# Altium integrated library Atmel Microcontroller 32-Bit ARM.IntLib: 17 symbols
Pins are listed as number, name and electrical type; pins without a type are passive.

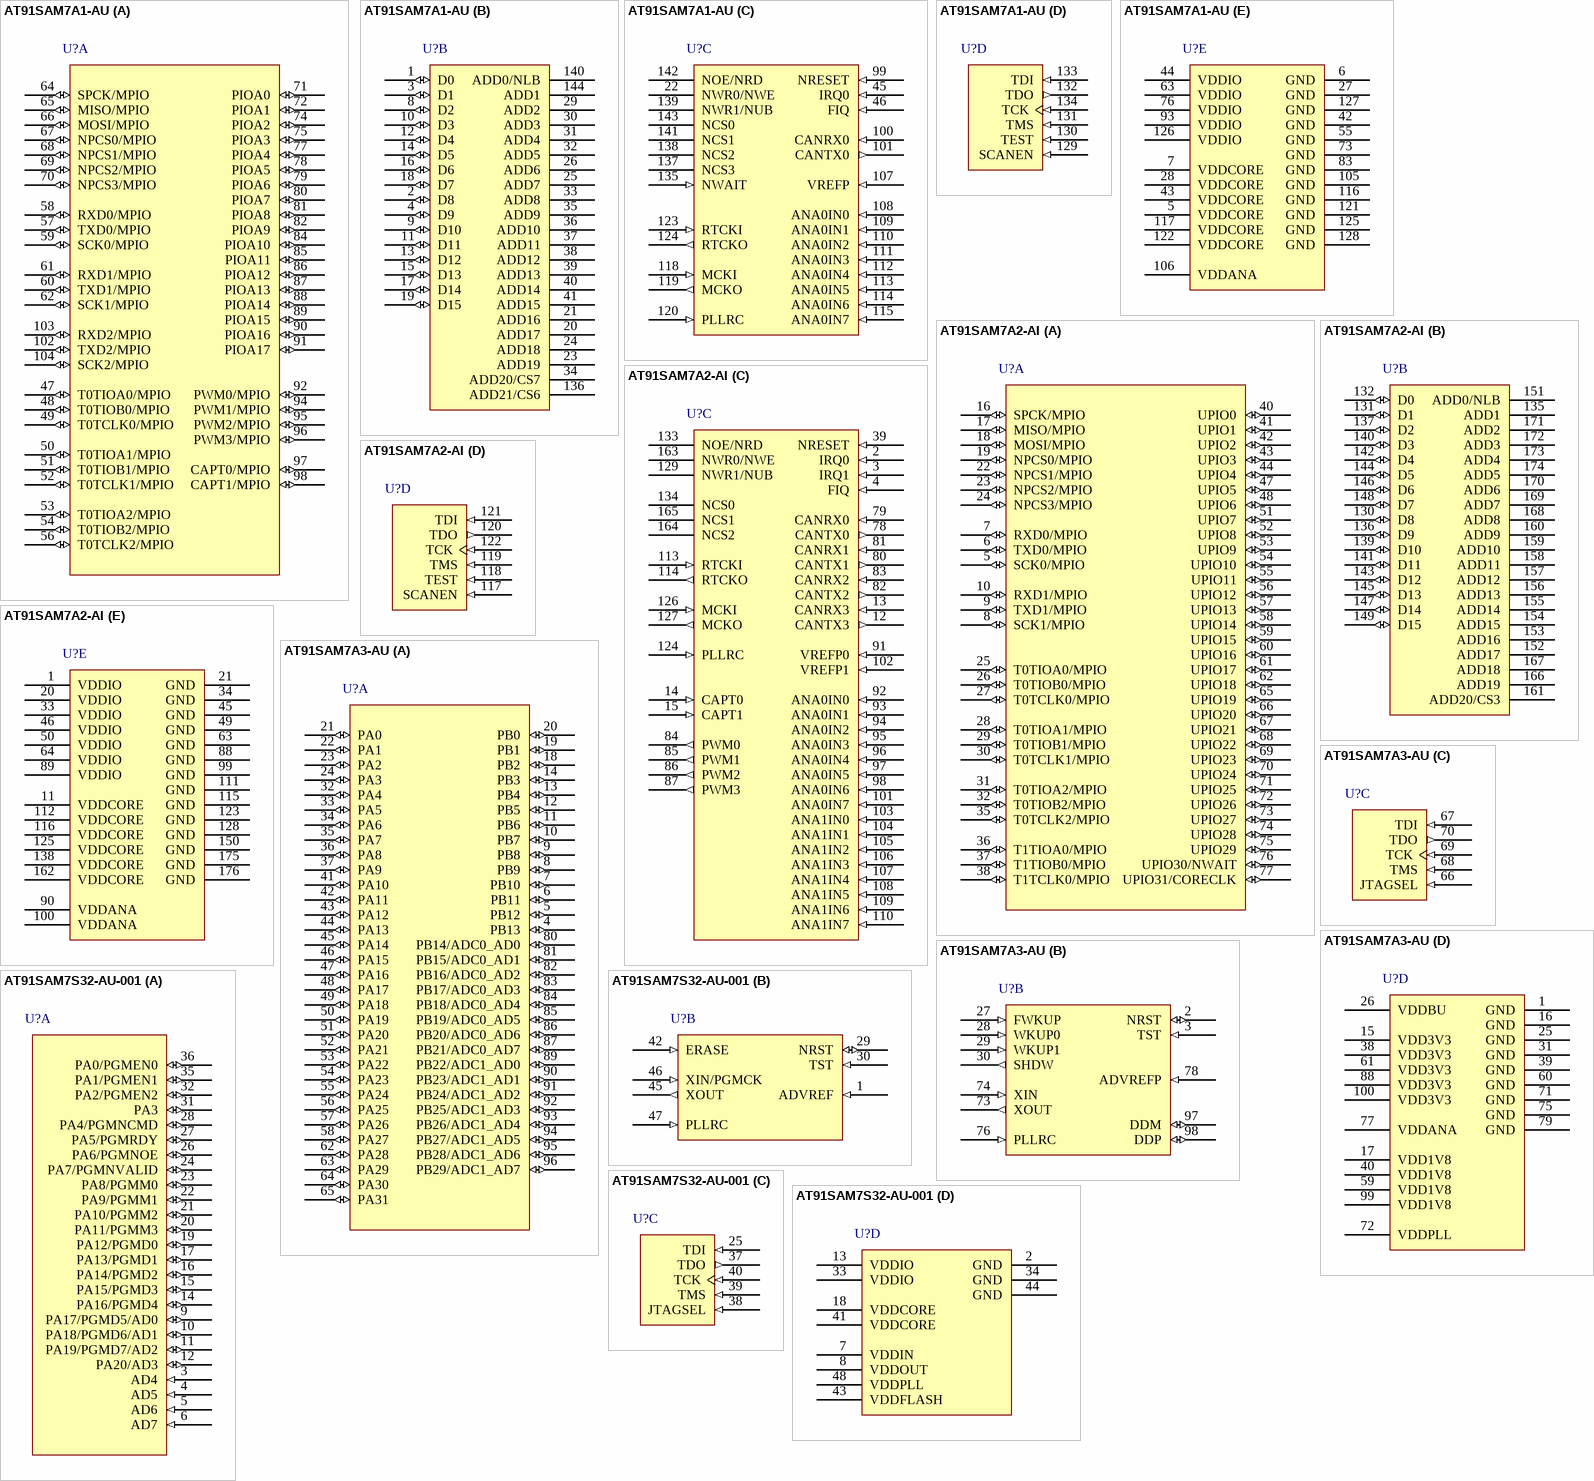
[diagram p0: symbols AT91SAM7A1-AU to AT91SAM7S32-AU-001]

## AT91SAM7A1-AU
designator U?
Smart ARM Microcontroller, ARM7TDMI 32-Bit RISC CPU, 4KB Internal RAM, 144-Pin LQFP, Industrial, Pb-Free
footprint 144AA_N (Thin QFP, 144-Leads, Body 20x20mm, Pitch 0.5mm, IPC Medium Density)
footprint 144AA_L (Thin QFP, 144-Leads, Body 20x20mm, Pitch 0.5mm, IPC High Density)
footprint 144AA_M (Thin QFP, 144-Leads, Body 20x20mm, Pitch 0.5mm, IPC Low Density)
part A pins: 47 T0TIOA0/MPIO (io), 48 T0TIOB0/MPIO (io), 49 T0TCLK0/MPIO (io), 50 T0TIOA1/MPIO (io), 51 T0TIOB1/MPIO (io), 52 T0TCLK1/MPIO (io), 53 T0TIOA2/MPIO (io), 54 T0TIOB2/MPIO (io), 56 T0TCLK2/MPIO (io), 57 TXD0/MPIO (io), 58 RXD0/MPIO (io), 59 SCK0/MPIO (io), 60 TXD1/MPIO (io), 61 RXD1/MPIO (io), 62 SCK1/MPIO (io), 64 SPCK/MPIO (io), 65 MISO/MPIO (io), 66 MOSI/MPIO (io), 67 NPCS0/MPIO (io), 68 NPCS1/MPIO (io), 69 NPCS2/MPIO (io), 70 NPCS3/MPIO (io), 71 PIOA0 (io), 72 PIOA1 (io), 74 PIOA2 (io), 75 PIOA3 (io), 77 PIOA4 (io), 78 PIOA5 (io), 79 PIOA6 (io), 80 PIOA7 (io), 81 PIOA8 (io), 82 PIOA9 (io), 84 PIOA10 (io), 85 PIOA11 (io), 86 PIOA12 (io), 87 PIOA13 (io), 88 PIOA14 (io), 89 PIOA15 (io), 90 PIOA16 (io), 91 PIOA17 (io), 92 PWM0/MPIO (io), 94 PWM1/MPIO (io), 95 PWM2/MPIO (io), 96 PWM3/MPIO (io), 97 CAPT0/MPIO (io), 98 CAPT1/MPIO (io), 102 TXD2/MPIO (io), 103 RXD2/MPIO (io), 104 SCK2/MPIO (io)
part B pins: 1 D0 (io), 2 D8 (io), 3 D1 (io), 4 D9 (io), 8 D2 (io), 9 D10 (io), 10 D3 (io), 11 D11 (io), 12 D4 (io), 13 D12 (io), 14 D5 (io), 15 D13 (io), 16 D6 (io), 17 D14 (io), 18 D7 (io), 19 D15 (io), 20 ADD17 (hiz), 21 ADD16 (hiz), 23 ADD19 (hiz), 24 ADD18 (hiz), 25 ADD7 (hiz), 26 ADD6 (hiz), 29 ADD2 (hiz), 30 ADD3 (hiz), 31 ADD4 (hiz), 32 ADD5 (hiz), 33 ADD8 (hiz), 34 ADD20/CS7 (hiz), 35 ADD9 (hiz), 36 ADD10 (hiz), 37 ADD11 (hiz), 38 ADD12 (hiz), 39 ADD13 (hiz), 40 ADD14 (hiz), 41 ADD15 (hiz), 136 ADD21/CS6 (hiz), 140 ADD0/NLB (hiz), 144 ADD1 (hiz)
part C pins: 22 NWR0/NWE (hiz), 45 IRQ0 (in), 46 FIQ (in), 99 NRESET (in), 100 CANRX0 (in), 101 CANTX0 (out), 107 VREFP (in), 108 ANA0IN0 (in), 109 ANA0IN1 (in), 110 ANA0IN2 (in), 111 ANA0IN3 (in), 112 ANA0IN4 (in), 113 ANA0IN5 (in), 114 ANA0IN6 (in), 115 ANA0IN7 (in), 118 MCKI (in), 119 MCKO (out), 120 PLLRC (in), 123 RTCKI (in), 124 RTCKO (out), 135 NWAIT (in), 137 NCS3 (hiz), 138 NCS2 (hiz), 139 NWR1/NUB (hiz), 141 NCS1 (hiz), 142 NOE/NRD (hiz), 143 NCS0 (hiz)
part D pins: 129 SCANEN (in), 130 TEST (in), 131 TMS (in), 132 TDO (out), 133 TDI (in), 134 TCK (in)
part E pins: 5 VDDCORE (power), 6 GND (power), 7 VDDCORE (power), 27 GND (power), 28 VDDCORE (power), 42 GND (power), 43 VDDCORE (power), 44 VDDIO (power), 55 GND (power), 63 VDDIO (power), 73 GND (power), 76 VDDIO (power), 83 GND (power), 93 VDDIO (power), 105 GND (power), 106 VDDANA (power), 116 GND (power), 117 VDDCORE (power), 121 GND (power), 122 VDDCORE (power), 125 GND (power), 126 VDDIO (power), 127 GND (power), 128 GND (power)

## AT91SAM7A2-AI
designator U?
Smart ARM Microcontroller, ARM7TDMI 32-Bit RISC CPU, 16KB Internal SRAM, 176-Pin LQFP, Industrial
footprint LQFP176_N (Thin QFP, 176-Leads, Body 24x24mm, Pitch 0.5mm, IPC Medium Density)
footprint LQFP176_L (Thin QFP, 176-Leads, Body 24x24mm, Pitch 0.5mm, IPC High Density)
footprint LQFP176_M (Thin QFP, 176-Leads, Body 24x24mm, Pitch 0.5mm, IPC Low Density)
part A pins: 5 SCK0/MPIO (io), 6 TXD0/MPIO (io), 7 RXD0/MPIO (io), 8 SCK1/MPIO (io), 9 TXD1/MPIO (io), 10 RXD1/MPIO (io), 16 SPCK/MPIO (io), 17 MISO/MPIO (io), 18 MOSI/MPIO (io), 19 NPCS0/MPIO (io), 22 NPCS1/MPIO (io), 23 NPCS2/MPIO (io), 24 NPCS3/MPIO (io), 25 T0TIOA0/MPIO (io), 26 T0TIOB0/MPIO (io), 27 T0TCLK0/MPIO (io), 28 T0TIOA1/MPIO (io), 29 T0TIOB1/MPIO (io), 30 T0TCLK1/MPIO (io), 31 T0TIOA2/MPIO (io), 32 T0TIOB2/MPIO (io), 35 T0TCLK2/MPIO (io), 36 T1TIOA0/MPIO (io), 37 T1TIOB0/MPIO (io), 38 T1TCLK0/MPIO (io), 40 UPIO0 (io), 41 UPIO1 (io), 42 UPIO2 (io), 43 UPIO3 (io), 44 UPIO4 (io), 47 UPIO5 (io), 48 UPIO6 (io), 51 UPIO7 (io), 52 UPIO8 (io), 53 UPIO9 (io), 54 UPIO10 (io), 55 UPIO11 (io), 56 UPIO12 (io), 57 UPIO13 (io), 58 UPIO14 (io), 59 UPIO15 (io), 60 UPIO16 (io), 61 UPIO17 (io), 62 UPIO18 (io), 65 UPIO19 (io), 66 UPIO20 (io), 67 UPIO21 (io), 68 UPIO22 (io), 69 UPIO23 (io), 70 UPIO24 (io), 71 UPIO25 (io), 72 UPIO26 (io), 73 UPIO27 (io), 74 UPIO28 (io), 75 UPIO29 (io), 76 UPIO30/NWAIT (io), 77 UPIO31/CORECLK (io)
part B pins: 130 D8 (io), 131 D1 (io), 132 D0 (io), 135 ADD1 (hiz), 136 D9 (io), 137 D2 (io), 139 D10 (io), 140 D3 (io), 141 D11 (io), 142 D4 (io), 143 D12 (io), 144 D5 (io), 145 D13 (io), 146 D6 (io), 147 D14 (io), 148 D7 (io), 149 D15 (io), 151 ADD0/NLB (hiz), 152 ADD17 (hiz), 153 ADD16 (hiz), 154 ADD15 (hiz), 155 ADD14 (hiz), 156 ADD13 (hiz), 157 ADD12 (hiz), 158 ADD11 (hiz), 159 ADD10 (hiz), 160 ADD9 (hiz), 161 ADD20/CS3 (hiz), 166 ADD19 (hiz), 167 ADD18 (hiz), 168 ADD8 (hiz), 169 ADD7 (hiz), 170 ADD6 (hiz), 171 ADD2 (hiz), 172 ADD3 (hiz), 173 ADD4 (hiz), 174 ADD5 (hiz)
part C pins: 2 IRQ0 (in), 3 IRQ1 (in), 4 FIQ (in), 12 CANTX3 (out), 13 CANRX3 (in), 14 CAPT0 (in), 15 CAPT1 (in), 39 NRESET (in), 78 CANTX0 (out), 79 CANRX0 (in), 80 CANTX1 (out), 81 CANRX1 (in), 82 CANTX2 (out), 83 CANRX2 (in), 84 PWM0 (out), 85 PWM1 (out), 86 PWM2 (out), 87 PWM3 (out), 91 VREFP0 (in), 92 ANA0IN0 (in), 93 ANA0IN1 (in), 94 ANA0IN2 (in), 95 ANA0IN3 (in), 96 ANA0IN4 (in), 97 ANA0IN5 (in), 98 ANA0IN6 (in), 101 ANA0IN7 (in), 102 VREFP1 (in), 103 ANA1IN0 (in), 104 ANA1IN1 (in), 105 ANA1IN2 (in), 106 ANA1IN3 (in), 107 ANA1IN4 (in), 108 ANA1IN5 (in), 109 ANA1IN6 (in), 110 ANA1IN7 (in), 113 RTCKI (in), 114 RTCKO (out), 124 PLLRC (in), 126 MCKI (in), 127 MCKO (out), 129 NWR1/NUB (hiz), 133 NOE/NRD (hiz), 134 NCS0 (hiz), 163 NWR0/NWE (hiz), 164 NCS2 (hiz), 165 NCS1 (hiz)
part D pins: 117 SCANEN (in), 118 TEST (in), 119 TMS (in), 120 TDO (out), 121 TDI (in), 122 TCK (in)
part E pins: 1 VDDIO (power), 11 VDDCORE (power), 20 VDDIO (power), 21 GND (power), 33 VDDIO (power), 34 GND (power), 45 GND (power), 46 VDDIO (power), 49 GND (power), 50 VDDIO (power), 63 GND (power), 64 VDDIO (power), 88 GND (power), 89 VDDIO (power), 90 VDDANA (power), 99 GND (power), 100 VDDANA (power), 111 GND (power), 112 VDDCORE (power), 115 GND (power), 116 VDDCORE (power), 123 GND (power), 125 VDDCORE (power), 128 GND (power), 138 VDDCORE (power), 150 GND (power), 162 VDDCORE (power), 175 GND (power), 176 GND (power)

## AT91SAM7A3-AU
designator U?
Smart ARM Microcontroller, ARM7TDMI 32-Bit RISC CPU, 256KB Flash and 32KB SRAM, 100-Pin LQFP, Industrial, Pb-Free
footprint LQFP100_N (Thin QFP, 100-Leads, Body 14x14mm, Pitch 0.5mm, IPC Medium Density)
footprint LQFP100_L (Thin QFP, 100-Leads, Body 14x14mm, Pitch 0.5mm, IPC High Density)
footprint LQFP100_M (Thin QFP, 100-Leads, Body 14x14mm, Pitch 0.5mm, IPC Low Density)
part A pins: 4 PB13 (io), 5 PB12 (io), 6 PB11 (io), 7 PB10 (io), 8 PB9 (io), 9 PB8 (io), 10 PB7 (io), 11 PB6 (io), 12 PB5 (io), 13 PB4 (io), 14 PB3 (io), 18 PB2 (io), 19 PB1 (io), 20 PB0 (io), 21 PA0 (io), 22 PA1 (io), 23 PA2 (io), 24 PA3 (io), 32 PA4 (io), 33 PA5 (io), 34 PA6 (io), 35 PA7 (io), 36 PA8 (io), 37 PA9 (io), 41 PA10 (io), 42 PA11 (io), 43 PA12 (io), 44 PA13 (io), 45 PA14 (io), 46 PA15 (io), 47 PA16 (io), 48 PA17 (io), 49 PA18 (io), 50 PA19 (io), 51 PA20 (io), 52 PA21 (io), 53 PA22 (io), 54 PA23 (io), 55 PA24 (io), 56 PA25 (io), 57 PA26 (io), 58 PA27 (io), 62 PA28 (io), 63 PA29 (io), 64 PA30 (io), 65 PA31 (io), 80 PB14/ADC0_AD0 (io), 81 PB15/ADC0_AD1 (io), 82 PB16/ADC0_AD2 (io), 83 PB17/ADC0_AD3 (io), 84 PB18/ADC0_AD4 (io), 85 PB19/ADC0_AD5 (io), 86 PB20/ADC0_AD6 (io), 87 PB21/ADC0_AD7 (io), 89 PB22/ADC1_AD0 (io), 90 PB23/ADC1_AD1 (io), 91 PB24/ADC1_AD2 (io), 92 PB25/ADC1_AD3 (io), 93 PB26/ADC1_AD4 (io), 94 PB27/ADC1_AD5 (io), 95 PB28/ADC1_AD6 (io), 96 PB29/ADC1_AD7 (io)
part B pins: 2 NRST (io), 3 TST (in), 27 FWKUP (in), 28 WKUP0 (in), 29 WKUP1 (in), 30 SHDW (out), 73 XOUT (out), 74 XIN (in), 76 PLLRC (in), 78 ADVREFP (in), 97 DDM (io), 98 DDP (io)
part C pins: 66 JTAGSEL (in), 67 TDI (in), 68 TMS (in), 69 TCK (in), 70 TDO (out)
part D pins: 1 GND (power), 15 VDD3V3 (power), 16 GND (power), 17 VDD1V8 (power), 25 GND (power), 26 VDDBU (power), 31 GND (power), 38 VDD3V3 (power), 39 GND (power), 40 VDD1V8 (power), 59 VDD1V8 (power), 60 GND (power), 61 VDD3V3 (power), 71 GND (power), 72 VDDPLL (power), 75 GND (power), 77 VDDANA (power), 79 GND (power), 88 VDD3V3 (power), 99 VDD1V8 (power), 100 VDD3V3 (power)

## AT91SAM7S32-AU-001
designator U?
Smart ARM Microcontroller, ARM7TDMI 32-Bit RISC CPU, 32KB Flash and 8KB SRAM, 48-Pin LQFP, Industrial, Pb-Free
footprint 48A_N (Thin QFP, 48-Leads, Body 7x7mm, Pitch 0.5mm, IPC Medium Density)
footprint 48A_L (Thin QFP, 48-Leads, Body 7x7mm, Pitch 0.5mm, IPC High Density)
footprint 48A_M (Thin QFP, 48-Leads, Body 7x7mm, Pitch 0.5mm, IPC Low Density)
part A pins: 3 AD4 (in), 4 AD5 (in), 5 AD6 (in), 6 AD7 (in), 9 PA17/PGMD5/AD0 (io), 10 PA18/PGMD6/AD1 (io), 11 PA19/PGMD7/AD2 (io), 12 PA20/AD3 (io), 14 PA16/PGMD4 (io), 15 PA15/PGMD3 (io), 16 PA14/PGMD2 (io), 17 PA13/PGMD1 (io), 19 PA12/PGMD0 (io), 20 PA11/PGMM3 (io), 21 PA10/PGMM2 (io), 22 PA9/PGMM1 (io), 23 PA8/PGMM0 (io), 24 PA7/PGMNVALID (io), 26 PA6/PGMNOE (io), 27 PA5/PGMRDY (io), 28 PA4/PGMNCMD (io), 31 PA3 (io), 32 PA2/PGMEN2 (io), 35 PA1/PGMEN1 (io), 36 PA0/PGMEN0 (io)
part B pins: 1 ADVREF (in), 29 NRST (io), 30 TST (in), 42 ERASE (in), 45 XOUT (out), 46 XIN/PGMCK (in), 47 PLLRC (in)
part C pins: 25 TDI (in), 37 TDO (out), 38 JTAGSEL (in), 39 TMS (in), 40 TCK (in)
part D pins: 2 GND (power), 7 VDDIN (power), 8 VDDOUT (power), 13 VDDIO (power), 18 VDDCORE (power), 33 VDDIO (power), 34 GND (power), 41 VDDCORE (power), 43 VDDFLASH (power), 44 GND (power), 48 VDDPLL (power)

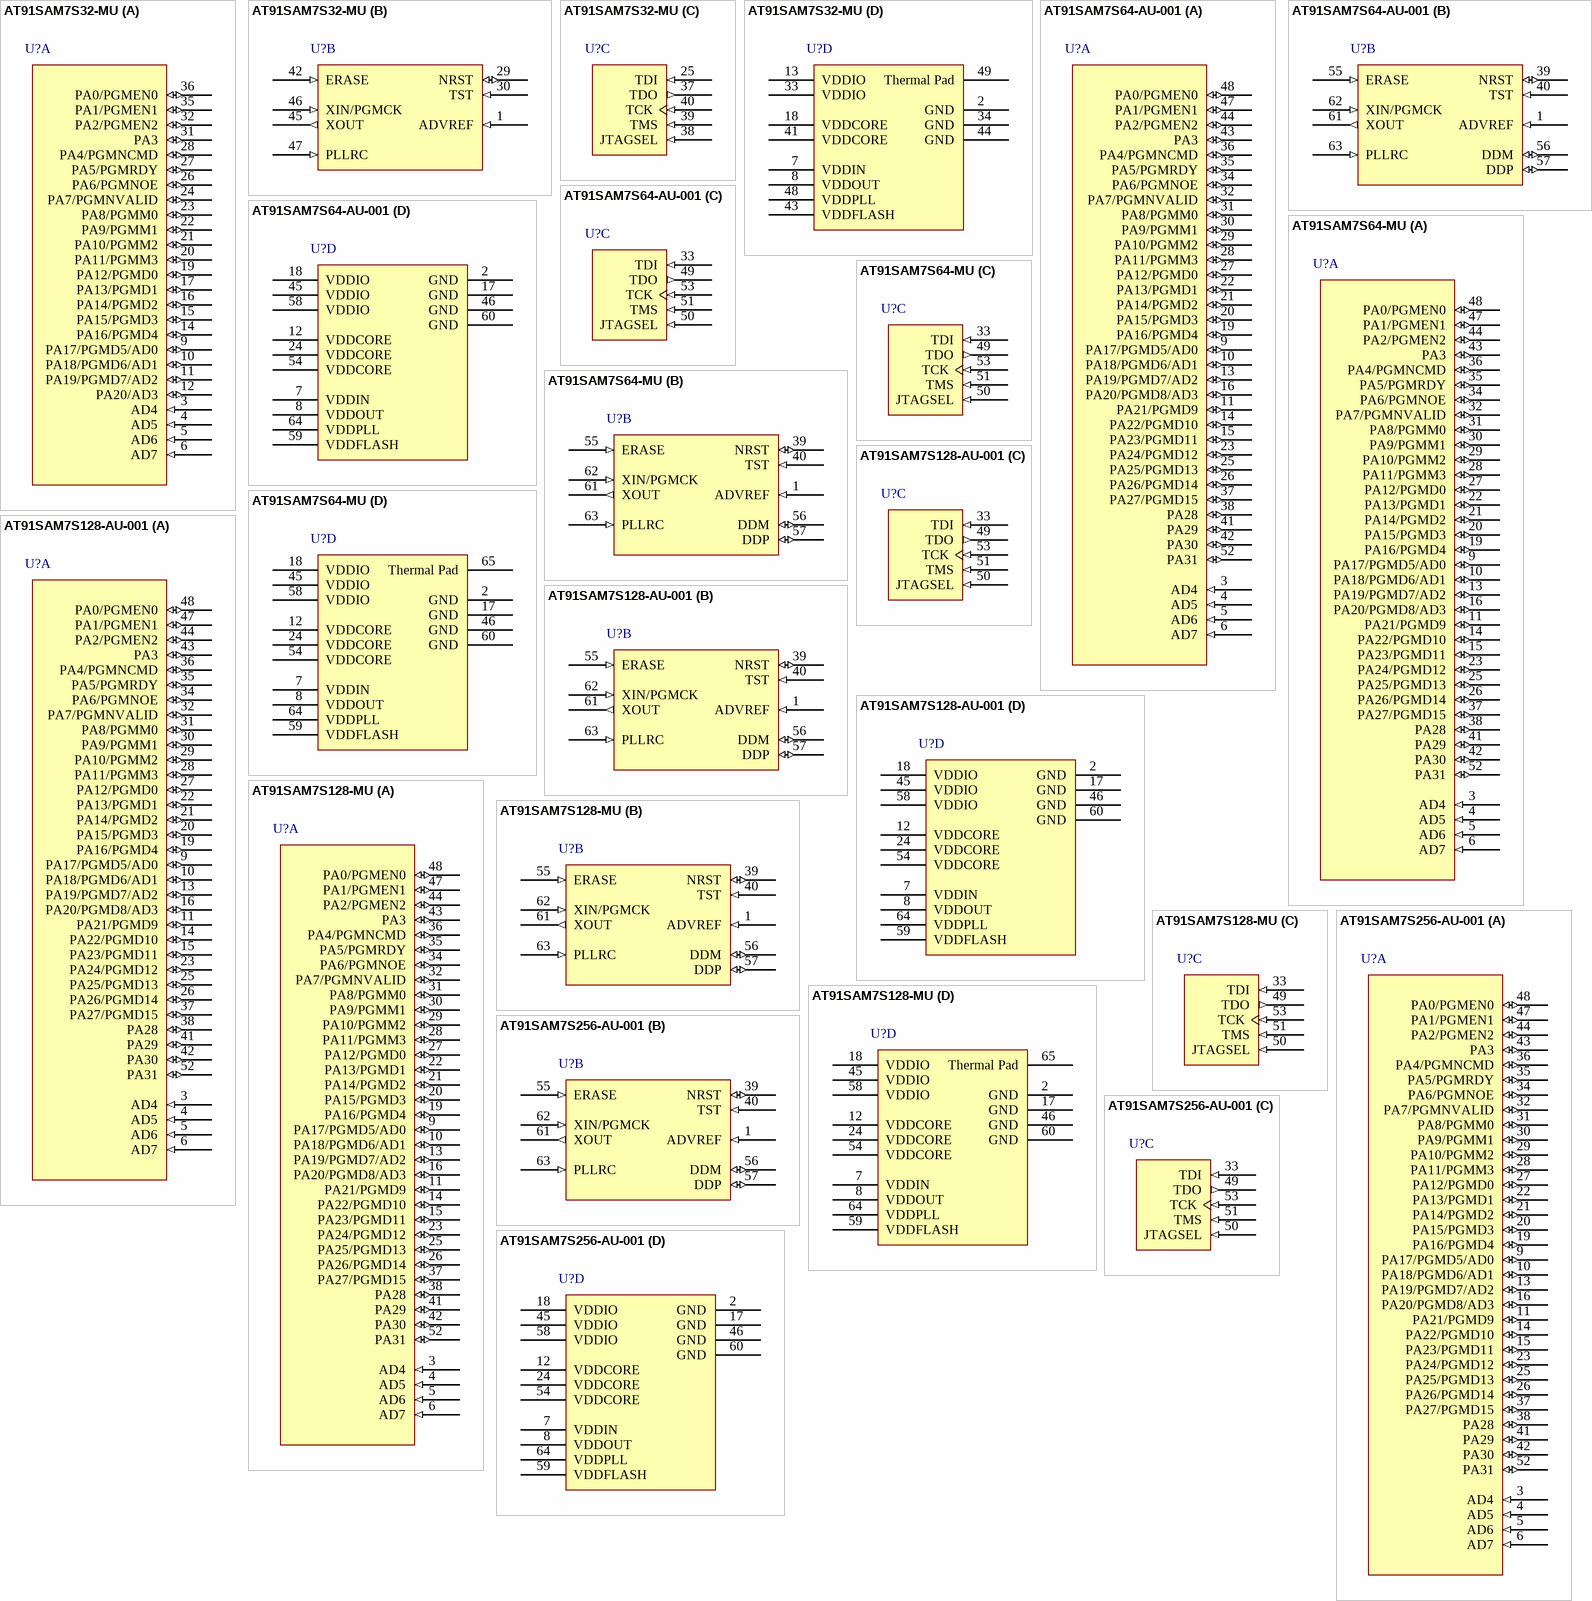
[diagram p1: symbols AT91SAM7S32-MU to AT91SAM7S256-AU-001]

## AT91SAM7S32-MU
designator U?
Smart ARM Microcontroller, ARM7TDMI 32-Bit RISC CPU, 32KB Flash and 8KB SRAM, 48-Pin QFN, Industrial, Pb-Free
footprint QFN48_N (QFN, 48-Leads, Body 7x7mm, Pitch 0.5mm, IPC Medium Density)
footprint QFN48_L (QFN, 48-Leads, Body 7x7mm, Pitch 0.5mm, IPC High Density)
footprint QFN48_M (QFN, 48-Leads, Body 7x7mm, Pitch 0.5mm, IPC Low Density)
part A pins: 3 AD4 (in), 4 AD5 (in), 5 AD6 (in), 6 AD7 (in), 9 PA17/PGMD5/AD0 (io), 10 PA18/PGMD6/AD1 (io), 11 PA19/PGMD7/AD2 (io), 12 PA20/AD3 (io), 14 PA16/PGMD4 (io), 15 PA15/PGMD3 (io), 16 PA14/PGMD2 (io), 17 PA13/PGMD1 (io), 19 PA12/PGMD0 (io), 20 PA11/PGMM3 (io), 21 PA10/PGMM2 (io), 22 PA9/PGMM1 (io), 23 PA8/PGMM0 (io), 24 PA7/PGMNVALID (io), 26 PA6/PGMNOE (io), 27 PA5/PGMRDY (io), 28 PA4/PGMNCMD (io), 31 PA3 (io), 32 PA2/PGMEN2 (io), 35 PA1/PGMEN1 (io), 36 PA0/PGMEN0 (io)
part B pins: 1 ADVREF (in), 29 NRST (io), 30 TST (in), 42 ERASE (in), 45 XOUT (out), 46 XIN/PGMCK (in), 47 PLLRC (in)
part C pins: 25 TDI (in), 37 TDO (out), 38 JTAGSEL (in), 39 TMS (in), 40 TCK (in)
part D pins: 2 GND (power), 7 VDDIN (power), 8 VDDOUT (power), 13 VDDIO (power), 18 VDDCORE (power), 33 VDDIO (power), 34 GND (power), 41 VDDCORE (power), 43 VDDFLASH (power), 44 GND (power), 48 VDDPLL (power), 49 Thermal Pad (power)

## AT91SAM7S64-AU-001
designator U?
Smart ARM Microcontroller, ARM7TDMI 32-Bit RISC CPU, 64KB Flash and 16KB SRAM, 64-Pin LQFP, Industrial, Pb-Free
footprint LQFP64_N (Thin QFP, 64-Leads, Body 10x10mm, Pitch 0.5mm, IPC Medium Density)
footprint LQFP64_L (Thin QFP, 64-Leads, Body 10x10mm, Pitch 0.5mm, IPC High Density)
footprint LQFP64_M (Thin QFP, 64-Leads, Body 10x10mm, Pitch 0.5mm, IPC Low Density)
part A pins: 3 AD4 (in), 4 AD5 (in), 5 AD6 (in), 6 AD7 (in), 9 PA17/PGMD5/AD0 (io), 10 PA18/PGMD6/AD1 (io), 11 PA21/PGMD9 (io), 13 PA19/PGMD7/AD2 (io), 14 PA22/PGMD10 (io), 15 PA23/PGMD11 (io), 16 PA20/PGMD8/AD3 (io), 19 PA16/PGMD4 (io), 20 PA15/PGMD3 (io), 21 PA14/PGMD2 (io), 22 PA13/PGMD1 (io), 23 PA24/PGMD12 (io), 25 PA25/PGMD13 (io), 26 PA26/PGMD14 (io), 27 PA12/PGMD0 (io), 28 PA11/PGMM3 (io), 29 PA10/PGMM2 (io), 30 PA9/PGMM1 (io), 31 PA8/PGMM0 (io), 32 PA7/PGMNVALID (io), 34 PA6/PGMNOE (io), 35 PA5/PGMRDY (io), 36 PA4/PGMNCMD (io), 37 PA27/PGMD15 (io), 38 PA28 (io), 41 PA29 (io), 42 PA30 (io), 43 PA3 (io), 44 PA2/PGMEN2 (io), 47 PA1/PGMEN1 (io), 48 PA0/PGMEN0 (io), 52 PA31 (io)
part B pins: 1 ADVREF (in), 39 NRST (io), 40 TST (in), 55 ERASE (in), 56 DDM (io), 57 DDP (io), 61 XOUT (out), 62 XIN/PGMCK (in), 63 PLLRC (in)
part C pins: 33 TDI (in), 49 TDO (out), 50 JTAGSEL (in), 51 TMS (in), 53 TCK (in)
part D pins: 2 GND (power), 7 VDDIN (power), 8 VDDOUT (power), 12 VDDCORE (power), 17 GND (power), 18 VDDIO (power), 24 VDDCORE (power), 45 VDDIO (power), 46 GND (power), 54 VDDCORE (power), 58 VDDIO (power), 59 VDDFLASH (power), 60 GND (power), 64 VDDPLL (power)

## AT91SAM7S64-MU
designator U?
Smart ARM Microcontroller, ARM7TDMI 32-Bit RISC CPU, 64KB Flash and 16KB SRAM, 64-Pin QFN, Industrial, Pb-Free
footprint QFN64_N (QFN, 64-Leads, Body 9x9mm, Pitch 0.5mm, IPC Medium Density)
footprint QFN64_L (QFN, 64-Leads, Body 9x9mm, Pitch 0.5mm, IPC High Density)
footprint QFN64_M (QFN, 64-Leads, Body 9x9mm, Pitch 0.5mm, IPC Low Density)
part A pins: 3 AD4 (in), 4 AD5 (in), 5 AD6 (in), 6 AD7 (in), 9 PA17/PGMD5/AD0 (io), 10 PA18/PGMD6/AD1 (io), 11 PA21/PGMD9 (io), 13 PA19/PGMD7/AD2 (io), 14 PA22/PGMD10 (io), 15 PA23/PGMD11 (io), 16 PA20/PGMD8/AD3 (io), 19 PA16/PGMD4 (io), 20 PA15/PGMD3 (io), 21 PA14/PGMD2 (io), 22 PA13/PGMD1 (io), 23 PA24/PGMD12 (io), 25 PA25/PGMD13 (io), 26 PA26/PGMD14 (io), 27 PA12/PGMD0 (io), 28 PA11/PGMM3 (io), 29 PA10/PGMM2 (io), 30 PA9/PGMM1 (io), 31 PA8/PGMM0 (io), 32 PA7/PGMNVALID (io), 34 PA6/PGMNOE (io), 35 PA5/PGMRDY (io), 36 PA4/PGMNCMD (io), 37 PA27/PGMD15 (io), 38 PA28 (io), 41 PA29 (io), 42 PA30 (io), 43 PA3 (io), 44 PA2/PGMEN2 (io), 47 PA1/PGMEN1 (io), 48 PA0/PGMEN0 (io), 52 PA31 (io)
part B pins: 1 ADVREF (in), 39 NRST (io), 40 TST (in), 55 ERASE (in), 56 DDM (io), 57 DDP (io), 61 XOUT (out), 62 XIN/PGMCK (in), 63 PLLRC (in)
part C pins: 33 TDI (in), 49 TDO (out), 50 JTAGSEL (in), 51 TMS (in), 53 TCK (in)
part D pins: 2 GND (power), 7 VDDIN (power), 8 VDDOUT (power), 12 VDDCORE (power), 17 GND (power), 18 VDDIO (power), 24 VDDCORE (power), 45 VDDIO (power), 46 GND (power), 54 VDDCORE (power), 58 VDDIO (power), 59 VDDFLASH (power), 60 GND (power), 64 VDDPLL (power), 65 Thermal Pad (power)

## AT91SAM7S128-AU-001
designator U?
Smart ARM Microcontroller, ARM7TDMI 32-Bit RISC CPU, 128KB Flash and 32KB SRAM, 64-Pin LQFP, Industrial, Pb-Free
footprint LQFP64_N (Thin QFP, 64-Leads, Body 10x10mm, Pitch 0.5mm, IPC Medium Density)
footprint LQFP64_L (Thin QFP, 64-Leads, Body 10x10mm, Pitch 0.5mm, IPC High Density)
footprint LQFP64_M (Thin QFP, 64-Leads, Body 10x10mm, Pitch 0.5mm, IPC Low Density)
part A pins: 3 AD4 (in), 4 AD5 (in), 5 AD6 (in), 6 AD7 (in), 9 PA17/PGMD5/AD0 (io), 10 PA18/PGMD6/AD1 (io), 11 PA21/PGMD9 (io), 13 PA19/PGMD7/AD2 (io), 14 PA22/PGMD10 (io), 15 PA23/PGMD11 (io), 16 PA20/PGMD8/AD3 (io), 19 PA16/PGMD4 (io), 20 PA15/PGMD3 (io), 21 PA14/PGMD2 (io), 22 PA13/PGMD1 (io), 23 PA24/PGMD12 (io), 25 PA25/PGMD13 (io), 26 PA26/PGMD14 (io), 27 PA12/PGMD0 (io), 28 PA11/PGMM3 (io), 29 PA10/PGMM2 (io), 30 PA9/PGMM1 (io), 31 PA8/PGMM0 (io), 32 PA7/PGMNVALID (io), 34 PA6/PGMNOE (io), 35 PA5/PGMRDY (io), 36 PA4/PGMNCMD (io), 37 PA27/PGMD15 (io), 38 PA28 (io), 41 PA29 (io), 42 PA30 (io), 43 PA3 (io), 44 PA2/PGMEN2 (io), 47 PA1/PGMEN1 (io), 48 PA0/PGMEN0 (io), 52 PA31 (io)
part B pins: 1 ADVREF (in), 39 NRST (io), 40 TST (in), 55 ERASE (in), 56 DDM (io), 57 DDP (io), 61 XOUT (out), 62 XIN/PGMCK (in), 63 PLLRC (in)
part C pins: 33 TDI (in), 49 TDO (out), 50 JTAGSEL (in), 51 TMS (in), 53 TCK (in)
part D pins: 2 GND (power), 7 VDDIN (power), 8 VDDOUT (power), 12 VDDCORE (power), 17 GND (power), 18 VDDIO (power), 24 VDDCORE (power), 45 VDDIO (power), 46 GND (power), 54 VDDCORE (power), 58 VDDIO (power), 59 VDDFLASH (power), 60 GND (power), 64 VDDPLL (power)

## AT91SAM7S128-MU
designator U?
Smart ARM Microcontroller, ARM7TDMI 32-Bit RISC CPU, 128KB Flash and 32KB SRAM, 64-Pin QFN, Industrial, Pb-Free
footprint QFN64_N (QFN, 64-Leads, Body 9x9mm, Pitch 0.5mm, IPC Medium Density)
footprint QFN64_L (QFN, 64-Leads, Body 9x9mm, Pitch 0.5mm, IPC High Density)
footprint QFN64_M (QFN, 64-Leads, Body 9x9mm, Pitch 0.5mm, IPC Low Density)
part A pins: 3 AD4 (in), 4 AD5 (in), 5 AD6 (in), 6 AD7 (in), 9 PA17/PGMD5/AD0 (io), 10 PA18/PGMD6/AD1 (io), 11 PA21/PGMD9 (io), 13 PA19/PGMD7/AD2 (io), 14 PA22/PGMD10 (io), 15 PA23/PGMD11 (io), 16 PA20/PGMD8/AD3 (io), 19 PA16/PGMD4 (io), 20 PA15/PGMD3 (io), 21 PA14/PGMD2 (io), 22 PA13/PGMD1 (io), 23 PA24/PGMD12 (io), 25 PA25/PGMD13 (io), 26 PA26/PGMD14 (io), 27 PA12/PGMD0 (io), 28 PA11/PGMM3 (io), 29 PA10/PGMM2 (io), 30 PA9/PGMM1 (io), 31 PA8/PGMM0 (io), 32 PA7/PGMNVALID (io), 34 PA6/PGMNOE (io), 35 PA5/PGMRDY (io), 36 PA4/PGMNCMD (io), 37 PA27/PGMD15 (io), 38 PA28 (io), 41 PA29 (io), 42 PA30 (io), 43 PA3 (io), 44 PA2/PGMEN2 (io), 47 PA1/PGMEN1 (io), 48 PA0/PGMEN0 (io), 52 PA31 (io)
part B pins: 1 ADVREF (in), 39 NRST (io), 40 TST (in), 55 ERASE (in), 56 DDM (io), 57 DDP (io), 61 XOUT (out), 62 XIN/PGMCK (in), 63 PLLRC (in)
part C pins: 33 TDI (in), 49 TDO (out), 50 JTAGSEL (in), 51 TMS (in), 53 TCK (in)
part D pins: 2 GND (power), 7 VDDIN (power), 8 VDDOUT (power), 12 VDDCORE (power), 17 GND (power), 18 VDDIO (power), 24 VDDCORE (power), 45 VDDIO (power), 46 GND (power), 54 VDDCORE (power), 58 VDDIO (power), 59 VDDFLASH (power), 60 GND (power), 64 VDDPLL (power), 65 Thermal Pad (power)

## AT91SAM7S256-AU-001
designator U?
Smart ARM Microcontroller, ARM7TDMI 32-Bit RISC CPU, 256KB Flash and 64KB SRAM, 64-Pin LQFP, Industrial, Pb-Free
footprint LQFP64_N (Thin QFP, 64-Leads, Body 10x10mm, Pitch 0.5mm, IPC Medium Density)
footprint LQFP64_L (Thin QFP, 64-Leads, Body 10x10mm, Pitch 0.5mm, IPC High Density)
footprint LQFP64_M (Thin QFP, 64-Leads, Body 10x10mm, Pitch 0.5mm, IPC Low Density)
part A pins: 3 AD4 (in), 4 AD5 (in), 5 AD6 (in), 6 AD7 (in), 9 PA17/PGMD5/AD0 (io), 10 PA18/PGMD6/AD1 (io), 11 PA21/PGMD9 (io), 13 PA19/PGMD7/AD2 (io), 14 PA22/PGMD10 (io), 15 PA23/PGMD11 (io), 16 PA20/PGMD8/AD3 (io), 19 PA16/PGMD4 (io), 20 PA15/PGMD3 (io), 21 PA14/PGMD2 (io), 22 PA13/PGMD1 (io), 23 PA24/PGMD12 (io), 25 PA25/PGMD13 (io), 26 PA26/PGMD14 (io), 27 PA12/PGMD0 (io), 28 PA11/PGMM3 (io), 29 PA10/PGMM2 (io), 30 PA9/PGMM1 (io), 31 PA8/PGMM0 (io), 32 PA7/PGMNVALID (io), 34 PA6/PGMNOE (io), 35 PA5/PGMRDY (io), 36 PA4/PGMNCMD (io), 37 PA27/PGMD15 (io), 38 PA28 (io), 41 PA29 (io), 42 PA30 (io), 43 PA3 (io), 44 PA2/PGMEN2 (io), 47 PA1/PGMEN1 (io), 48 PA0/PGMEN0 (io), 52 PA31 (io)
part B pins: 1 ADVREF (in), 39 NRST (io), 40 TST (in), 55 ERASE (in), 56 DDM (io), 57 DDP (io), 61 XOUT (out), 62 XIN/PGMCK (in), 63 PLLRC (in)
part C pins: 33 TDI (in), 49 TDO (out), 50 JTAGSEL (in), 51 TMS (in), 53 TCK (in)
part D pins: 2 GND (power), 7 VDDIN (power), 8 VDDOUT (power), 12 VDDCORE (power), 17 GND (power), 18 VDDIO (power), 24 VDDCORE (power), 45 VDDIO (power), 46 GND (power), 54 VDDCORE (power), 58 VDDIO (power), 59 VDDFLASH (power), 60 GND (power), 64 VDDPLL (power)

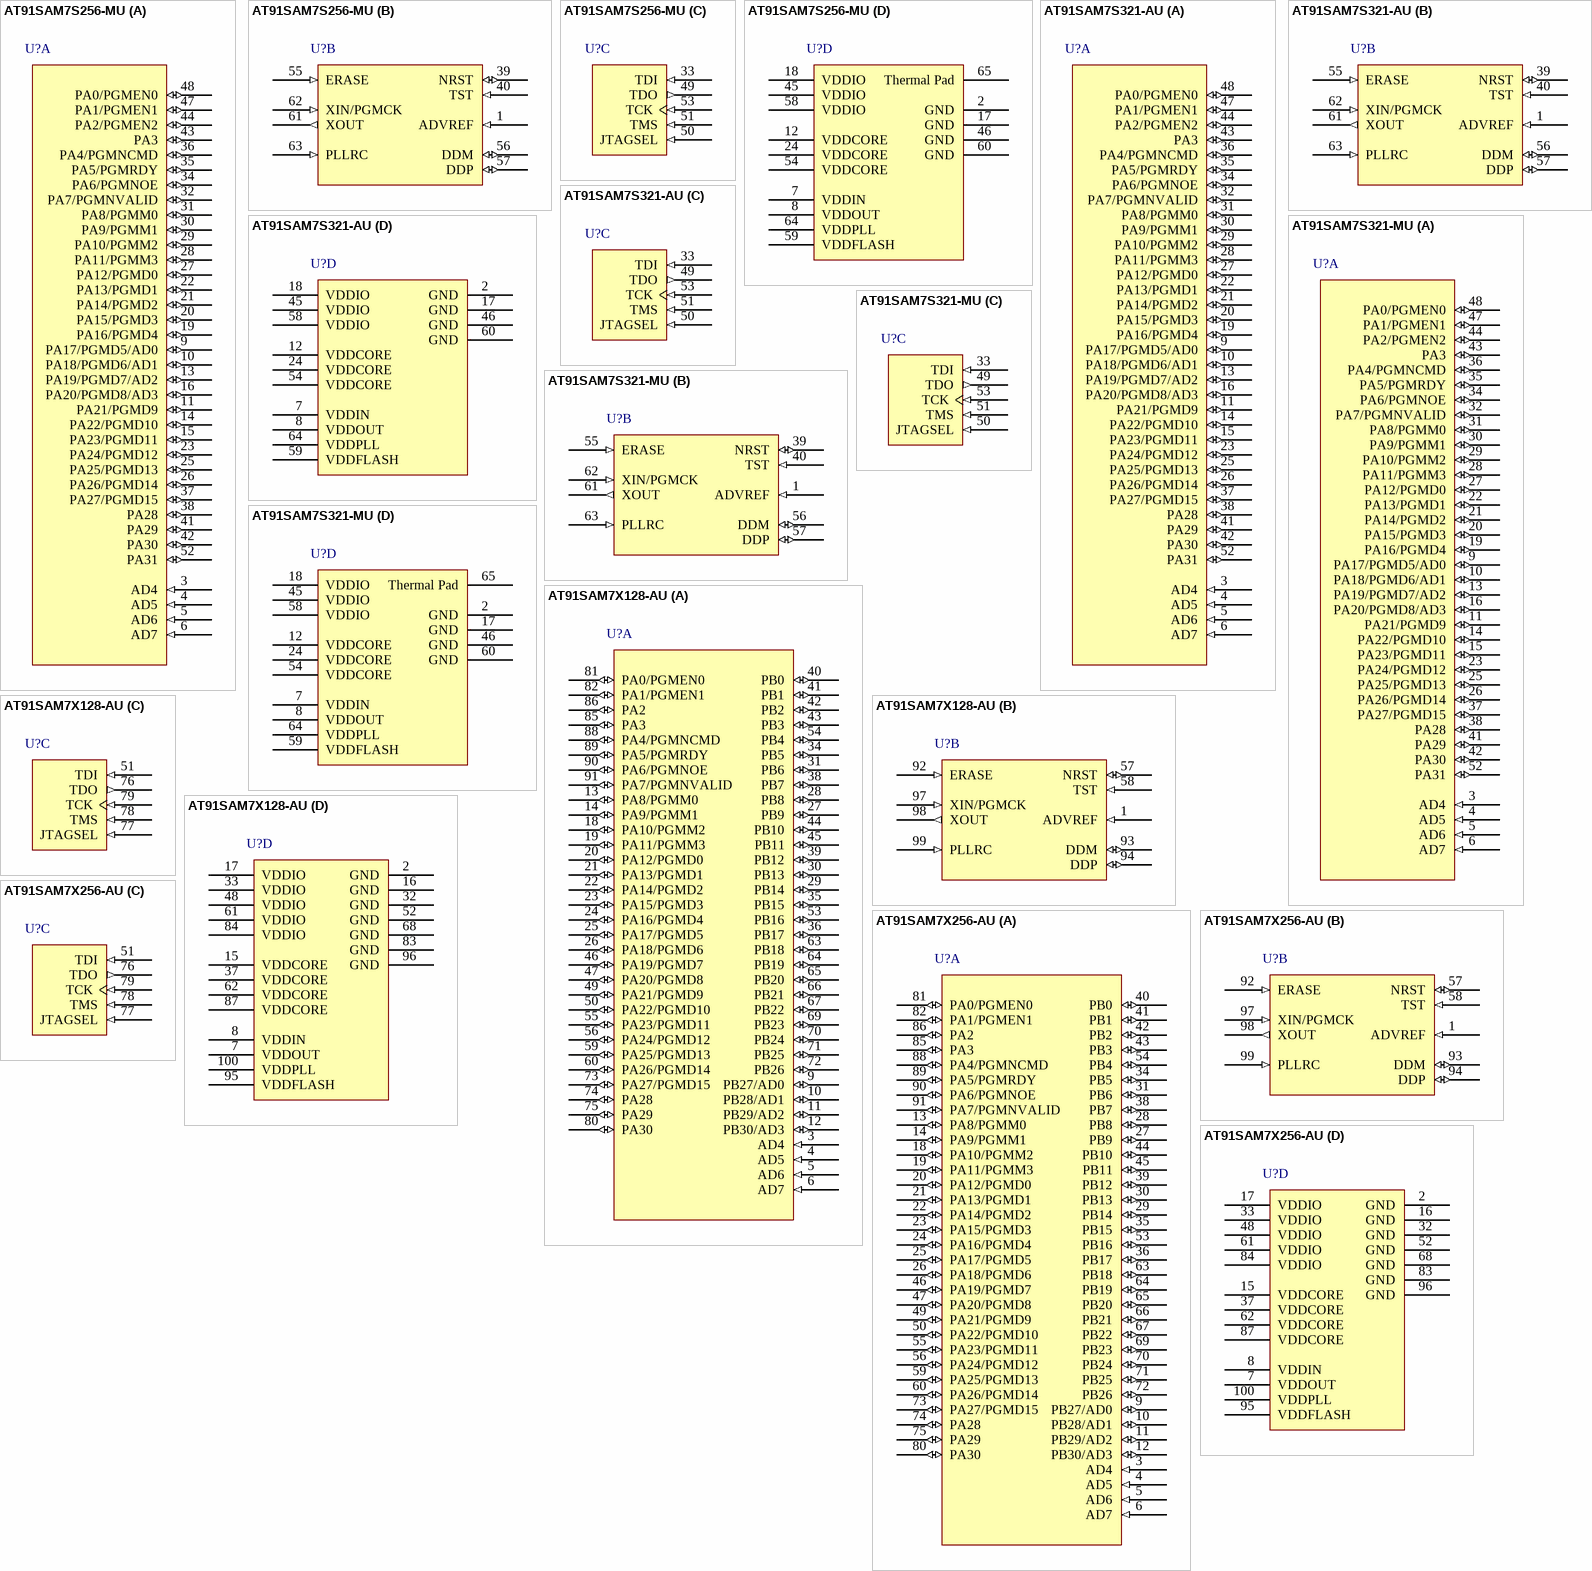
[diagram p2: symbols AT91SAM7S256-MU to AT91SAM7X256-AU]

## AT91SAM7S256-MU
designator U?
Smart ARM Microcontroller, ARM7TDMI 32-Bit RISC CPU, 256KB Flash and 64KB SRAM, 64-Pin QFN, Industrial, Pb-Free
footprint QFN64_N (QFN, 64-Leads, Body 9x9mm, Pitch 0.5mm, IPC Medium Density)
footprint QFN64_L (QFN, 64-Leads, Body 9x9mm, Pitch 0.5mm, IPC High Density)
footprint QFN64_M (QFN, 64-Leads, Body 9x9mm, Pitch 0.5mm, IPC Low Density)
part A pins: 3 AD4 (in), 4 AD5 (in), 5 AD6 (in), 6 AD7 (in), 9 PA17/PGMD5/AD0 (io), 10 PA18/PGMD6/AD1 (io), 11 PA21/PGMD9 (io), 13 PA19/PGMD7/AD2 (io), 14 PA22/PGMD10 (io), 15 PA23/PGMD11 (io), 16 PA20/PGMD8/AD3 (io), 19 PA16/PGMD4 (io), 20 PA15/PGMD3 (io), 21 PA14/PGMD2 (io), 22 PA13/PGMD1 (io), 23 PA24/PGMD12 (io), 25 PA25/PGMD13 (io), 26 PA26/PGMD14 (io), 27 PA12/PGMD0 (io), 28 PA11/PGMM3 (io), 29 PA10/PGMM2 (io), 30 PA9/PGMM1 (io), 31 PA8/PGMM0 (io), 32 PA7/PGMNVALID (io), 34 PA6/PGMNOE (io), 35 PA5/PGMRDY (io), 36 PA4/PGMNCMD (io), 37 PA27/PGMD15 (io), 38 PA28 (io), 41 PA29 (io), 42 PA30 (io), 43 PA3 (io), 44 PA2/PGMEN2 (io), 47 PA1/PGMEN1 (io), 48 PA0/PGMEN0 (io), 52 PA31 (io)
part B pins: 1 ADVREF (in), 39 NRST (io), 40 TST (in), 55 ERASE (in), 56 DDM (io), 57 DDP (io), 61 XOUT (out), 62 XIN/PGMCK (in), 63 PLLRC (in)
part C pins: 33 TDI (in), 49 TDO (out), 50 JTAGSEL (in), 51 TMS (in), 53 TCK (in)
part D pins: 2 GND (power), 7 VDDIN (power), 8 VDDOUT (power), 12 VDDCORE (power), 17 GND (power), 18 VDDIO (power), 24 VDDCORE (power), 45 VDDIO (power), 46 GND (power), 54 VDDCORE (power), 58 VDDIO (power), 59 VDDFLASH (power), 60 GND (power), 64 VDDPLL (power), 65 Thermal Pad (power)

## AT91SAM7S321-AU
designator U?
Smart ARM Microcontroller, ARM7TDMI 32-Bit RISC CPU, 32KB Flash and 8KB SRAM, 64-Pin LQFP, Industrial, Pb-Free
footprint LQFP64_N (Thin QFP, 64-Leads, Body 10x10mm, Pitch 0.5mm, IPC Medium Density)
footprint LQFP64_L (Thin QFP, 64-Leads, Body 10x10mm, Pitch 0.5mm, IPC High Density)
footprint LQFP64_M (Thin QFP, 64-Leads, Body 10x10mm, Pitch 0.5mm, IPC Low Density)
part A pins: 3 AD4 (in), 4 AD5 (in), 5 AD6 (in), 6 AD7 (in), 9 PA17/PGMD5/AD0 (io), 10 PA18/PGMD6/AD1 (io), 11 PA21/PGMD9 (io), 13 PA19/PGMD7/AD2 (io), 14 PA22/PGMD10 (io), 15 PA23/PGMD11 (io), 16 PA20/PGMD8/AD3 (io), 19 PA16/PGMD4 (io), 20 PA15/PGMD3 (io), 21 PA14/PGMD2 (io), 22 PA13/PGMD1 (io), 23 PA24/PGMD12 (io), 25 PA25/PGMD13 (io), 26 PA26/PGMD14 (io), 27 PA12/PGMD0 (io), 28 PA11/PGMM3 (io), 29 PA10/PGMM2 (io), 30 PA9/PGMM1 (io), 31 PA8/PGMM0 (io), 32 PA7/PGMNVALID (io), 34 PA6/PGMNOE (io), 35 PA5/PGMRDY (io), 36 PA4/PGMNCMD (io), 37 PA27/PGMD15 (io), 38 PA28 (io), 41 PA29 (io), 42 PA30 (io), 43 PA3 (io), 44 PA2/PGMEN2 (io), 47 PA1/PGMEN1 (io), 48 PA0/PGMEN0 (io), 52 PA31 (io)
part B pins: 1 ADVREF (in), 39 NRST (io), 40 TST (in), 55 ERASE (in), 56 DDM (io), 57 DDP (io), 61 XOUT (out), 62 XIN/PGMCK (in), 63 PLLRC (in)
part C pins: 33 TDI (in), 49 TDO (out), 50 JTAGSEL (in), 51 TMS (in), 53 TCK (in)
part D pins: 2 GND (power), 7 VDDIN (power), 8 VDDOUT (power), 12 VDDCORE (power), 17 GND (power), 18 VDDIO (power), 24 VDDCORE (power), 45 VDDIO (power), 46 GND (power), 54 VDDCORE (power), 58 VDDIO (power), 59 VDDFLASH (power), 60 GND (power), 64 VDDPLL (power)

## AT91SAM7S321-MU
designator U?
Smart ARM Microcontroller, ARM7TDMI 32-Bit RISC CPU, 32KB Flash and 8KB SRAM, 64-Pin QFN, Industrial, Pb-Free
footprint QFN64_N (QFN, 64-Leads, Body 9x9mm, Pitch 0.5mm, IPC Medium Density)
footprint QFN64_L (QFN, 64-Leads, Body 9x9mm, Pitch 0.5mm, IPC High Density)
footprint QFN64_M (QFN, 64-Leads, Body 9x9mm, Pitch 0.5mm, IPC Low Density)
part A pins: 3 AD4 (in), 4 AD5 (in), 5 AD6 (in), 6 AD7 (in), 9 PA17/PGMD5/AD0 (io), 10 PA18/PGMD6/AD1 (io), 11 PA21/PGMD9 (io), 13 PA19/PGMD7/AD2 (io), 14 PA22/PGMD10 (io), 15 PA23/PGMD11 (io), 16 PA20/PGMD8/AD3 (io), 19 PA16/PGMD4 (io), 20 PA15/PGMD3 (io), 21 PA14/PGMD2 (io), 22 PA13/PGMD1 (io), 23 PA24/PGMD12 (io), 25 PA25/PGMD13 (io), 26 PA26/PGMD14 (io), 27 PA12/PGMD0 (io), 28 PA11/PGMM3 (io), 29 PA10/PGMM2 (io), 30 PA9/PGMM1 (io), 31 PA8/PGMM0 (io), 32 PA7/PGMNVALID (io), 34 PA6/PGMNOE (io), 35 PA5/PGMRDY (io), 36 PA4/PGMNCMD (io), 37 PA27/PGMD15 (io), 38 PA28 (io), 41 PA29 (io), 42 PA30 (io), 43 PA3 (io), 44 PA2/PGMEN2 (io), 47 PA1/PGMEN1 (io), 48 PA0/PGMEN0 (io), 52 PA31 (io)
part B pins: 1 ADVREF (in), 39 NRST (io), 40 TST (in), 55 ERASE (in), 56 DDM (io), 57 DDP (io), 61 XOUT (out), 62 XIN/PGMCK (in), 63 PLLRC (in)
part C pins: 33 TDI (in), 49 TDO (out), 50 JTAGSEL (in), 51 TMS (in), 53 TCK (in)
part D pins: 2 GND (power), 7 VDDIN (power), 8 VDDOUT (power), 12 VDDCORE (power), 17 GND (power), 18 VDDIO (power), 24 VDDCORE (power), 45 VDDIO (power), 46 GND (power), 54 VDDCORE (power), 58 VDDIO (power), 59 VDDFLASH (power), 60 GND (power), 64 VDDPLL (power), 65 Thermal Pad (power)

## AT91SAM7X128-AU
designator U?
Smart ARM Microcontroller, ARM7TDMI 32-Bit RISC CPU, 128KB Flash and 32KB SRAM, 100-Pin LQFP, Industrial, Pb-Free
footprint LQFP100_N (Thin QFP, 100-Leads, Body 14x14mm, Pitch 0.5mm, IPC Medium Density)
footprint LQFP100_L (Thin QFP, 100-Leads, Body 14x14mm, Pitch 0.5mm, IPC High Density)
footprint LQFP100_M (Thin QFP, 100-Leads, Body 14x14mm, Pitch 0.5mm, IPC Low Density)
part A pins: 3 AD4 (in), 4 AD5 (in), 5 AD6 (in), 6 AD7 (in), 9 PB27/AD0 (io), 10 PB28/AD1 (io), 11 PB29/AD2 (io), 12 PB30/AD3 (io), 13 PA8/PGMM0 (io), 14 PA9/PGMM1 (io), 18 PA10/PGMM2 (io), 19 PA11/PGMM3 (io), 20 PA12/PGMD0 (io), 21 PA13/PGMD1 (io), 22 PA14/PGMD2 (io), 23 PA15/PGMD3 (io), 24 PA16/PGMD4 (io), 25 PA17/PGMD5 (io), 26 PA18/PGMD6 (io), 27 PB9 (io), 28 PB8 (io), 29 PB14 (io), 30 PB13 (io), 31 PB6 (io), 34 PB5 (io), 35 PB15 (io), 36 PB17 (io), 38 PB7 (io), 39 PB12 (io), 40 PB0 (io), 41 PB1 (io), 42 PB2 (io), 43 PB3 (io), 44 PB10 (io), 45 PB11 (io), 46 PA19/PGMD7 (io), 47 PA20/PGMD8 (io), 49 PA21/PGMD9 (io), 50 PA22/PGMD10 (io), 53 PB16 (io), 54 PB4 (io), 55 PA23/PGMD11 (io), 56 PA24/PGMD12 (io), 59 PA25/PGMD13 (io), 60 PA26/PGMD14 (io), 63 PB18 (io), 64 PB19 (io), 65 PB20 (io), 66 PB21 (io), 67 PB22 (io), 69 PB23 (io), 70 PB24 (io), 71 PB25 (io), 72 PB26 (io), 73 PA27/PGMD15 (io), 74 PA28 (io), 75 PA29 (io), 80 PA30 (io), 81 PA0/PGMEN0 (io), 82 PA1/PGMEN1 (io), 85 PA3 (io), 86 PA2 (io), 88 PA4/PGMNCMD (io), 89 PA5/PGMRDY (io), 90 PA6/PGMNOE (io), 91 PA7/PGMNVALID (io)
part B pins: 1 ADVREF (in), 57 NRST (io), 58 TST (in), 92 ERASE (in), 93 DDM (io), 94 DDP (io), 97 XIN/PGMCK (in), 98 XOUT (out), 99 PLLRC (in)
part C pins: 51 TDI (in), 76 TDO (out), 77 JTAGSEL (in), 78 TMS (in), 79 TCK (in)
part D pins: 2 GND (power), 7 VDDOUT (power), 8 VDDIN (power), 15 VDDCORE (power), 16 GND (power), 17 VDDIO (power), 32 GND (power), 33 VDDIO (power), 37 VDDCORE (power), 48 VDDIO (power), 52 GND (power), 61 VDDIO (power), 62 VDDCORE (power), 68 GND (power), 83 GND (power), 84 VDDIO (power), 87 VDDCORE (power), 95 VDDFLASH (power), 96 GND (power), 100 VDDPLL (power)

## AT91SAM7X256-AU
designator U?
Smart ARM Microcontroller, ARM7TDMI 32-Bit RISC CPU, 256KB Flash and 64KB SRAM, 100-Pin LQFP, Industrial, Pb-Free
footprint LQFP100_N (Thin QFP, 100-Leads, Body 14x14mm, Pitch 0.5mm, IPC Medium Density)
footprint LQFP100_L (Thin QFP, 100-Leads, Body 14x14mm, Pitch 0.5mm, IPC High Density)
footprint LQFP100_M (Thin QFP, 100-Leads, Body 14x14mm, Pitch 0.5mm, IPC Low Density)
part A pins: 3 AD4 (in), 4 AD5 (in), 5 AD6 (in), 6 AD7 (in), 9 PB27/AD0 (io), 10 PB28/AD1 (io), 11 PB29/AD2 (io), 12 PB30/AD3 (io), 13 PA8/PGMM0 (io), 14 PA9/PGMM1 (io), 18 PA10/PGMM2 (io), 19 PA11/PGMM3 (io), 20 PA12/PGMD0 (io), 21 PA13/PGMD1 (io), 22 PA14/PGMD2 (io), 23 PA15/PGMD3 (io), 24 PA16/PGMD4 (io), 25 PA17/PGMD5 (io), 26 PA18/PGMD6 (io), 27 PB9 (io), 28 PB8 (io), 29 PB14 (io), 30 PB13 (io), 31 PB6 (io), 34 PB5 (io), 35 PB15 (io), 36 PB17 (io), 38 PB7 (io), 39 PB12 (io), 40 PB0 (io), 41 PB1 (io), 42 PB2 (io), 43 PB3 (io), 44 PB10 (io), 45 PB11 (io), 46 PA19/PGMD7 (io), 47 PA20/PGMD8 (io), 49 PA21/PGMD9 (io), 50 PA22/PGMD10 (io), 53 PB16 (io), 54 PB4 (io), 55 PA23/PGMD11 (io), 56 PA24/PGMD12 (io), 59 PA25/PGMD13 (io), 60 PA26/PGMD14 (io), 63 PB18 (io), 64 PB19 (io), 65 PB20 (io), 66 PB21 (io), 67 PB22 (io), 69 PB23 (io), 70 PB24 (io), 71 PB25 (io), 72 PB26 (io), 73 PA27/PGMD15 (io), 74 PA28 (io), 75 PA29 (io), 80 PA30 (io), 81 PA0/PGMEN0 (io), 82 PA1/PGMEN1 (io), 85 PA3 (io), 86 PA2 (io), 88 PA4/PGMNCMD (io), 89 PA5/PGMRDY (io), 90 PA6/PGMNOE (io), 91 PA7/PGMNVALID (io)
part B pins: 1 ADVREF (in), 57 NRST (io), 58 TST (in), 92 ERASE (in), 93 DDM (io), 94 DDP (io), 97 XIN/PGMCK (in), 98 XOUT (out), 99 PLLRC (in)
part C pins: 51 TDI (in), 76 TDO (out), 77 JTAGSEL (in), 78 TMS (in), 79 TCK (in)
part D pins: 2 GND (power), 7 VDDOUT (power), 8 VDDIN (power), 15 VDDCORE (power), 16 GND (power), 17 VDDIO (power), 32 GND (power), 33 VDDIO (power), 37 VDDCORE (power), 48 VDDIO (power), 52 GND (power), 61 VDDIO (power), 62 VDDCORE (power), 68 GND (power), 83 GND (power), 84 VDDIO (power), 87 VDDCORE (power), 95 VDDFLASH (power), 96 GND (power), 100 VDDPLL (power)

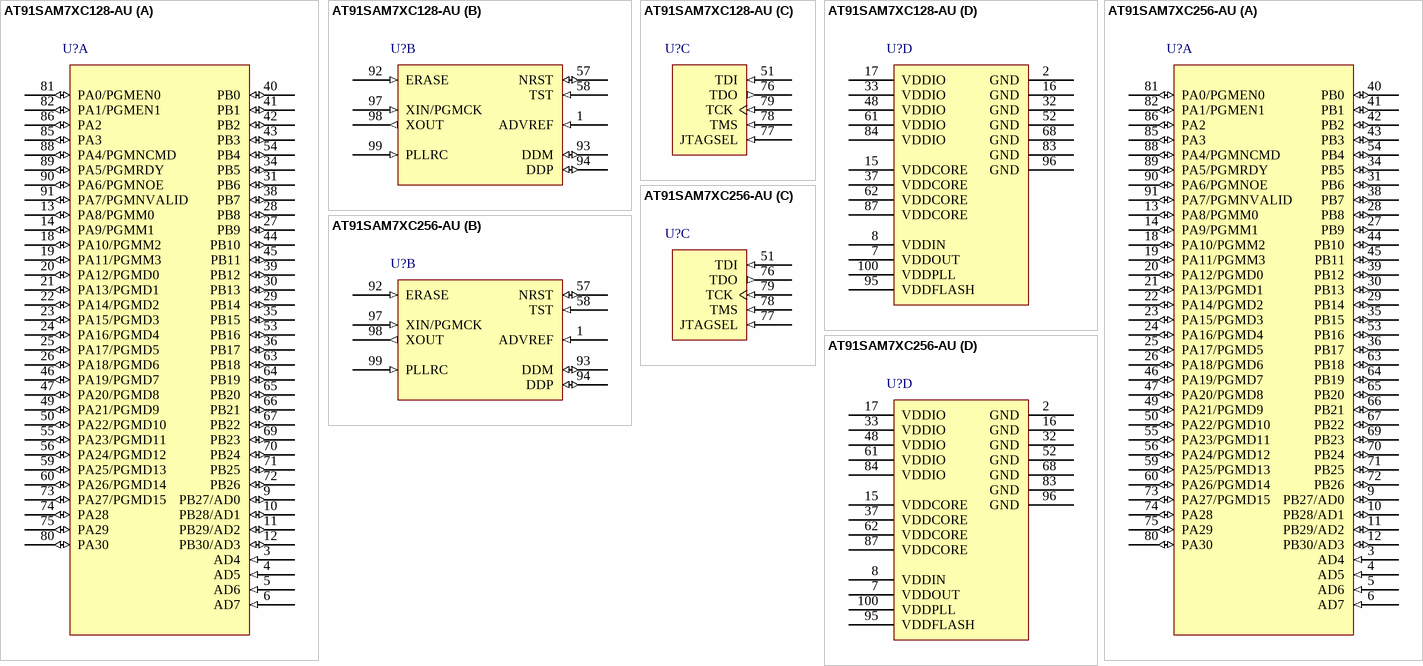
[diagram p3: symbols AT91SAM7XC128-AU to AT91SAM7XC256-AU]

## AT91SAM7XC128-AU
designator U?
Smart ARM Microcontroller, ARM7TDMI 32-Bit RISC CPU, 128KB Flash and 32KB SRAM, 100-Pin LQFP, Industrial, Pb-Free
footprint LQFP100_N (Thin QFP, 100-Leads, Body 14x14mm, Pitch 0.5mm, IPC Medium Density)
footprint LQFP100_L (Thin QFP, 100-Leads, Body 14x14mm, Pitch 0.5mm, IPC High Density)
footprint LQFP100_M (Thin QFP, 100-Leads, Body 14x14mm, Pitch 0.5mm, IPC Low Density)
part A pins: 3 AD4 (in), 4 AD5 (in), 5 AD6 (in), 6 AD7 (in), 9 PB27/AD0 (io), 10 PB28/AD1 (io), 11 PB29/AD2 (io), 12 PB30/AD3 (io), 13 PA8/PGMM0 (io), 14 PA9/PGMM1 (io), 18 PA10/PGMM2 (io), 19 PA11/PGMM3 (io), 20 PA12/PGMD0 (io), 21 PA13/PGMD1 (io), 22 PA14/PGMD2 (io), 23 PA15/PGMD3 (io), 24 PA16/PGMD4 (io), 25 PA17/PGMD5 (io), 26 PA18/PGMD6 (io), 27 PB9 (io), 28 PB8 (io), 29 PB14 (io), 30 PB13 (io), 31 PB6 (io), 34 PB5 (io), 35 PB15 (io), 36 PB17 (io), 38 PB7 (io), 39 PB12 (io), 40 PB0 (io), 41 PB1 (io), 42 PB2 (io), 43 PB3 (io), 44 PB10 (io), 45 PB11 (io), 46 PA19/PGMD7 (io), 47 PA20/PGMD8 (io), 49 PA21/PGMD9 (io), 50 PA22/PGMD10 (io), 53 PB16 (io), 54 PB4 (io), 55 PA23/PGMD11 (io), 56 PA24/PGMD12 (io), 59 PA25/PGMD13 (io), 60 PA26/PGMD14 (io), 63 PB18 (io), 64 PB19 (io), 65 PB20 (io), 66 PB21 (io), 67 PB22 (io), 69 PB23 (io), 70 PB24 (io), 71 PB25 (io), 72 PB26 (io), 73 PA27/PGMD15 (io), 74 PA28 (io), 75 PA29 (io), 80 PA30 (io), 81 PA0/PGMEN0 (io), 82 PA1/PGMEN1 (io), 85 PA3 (io), 86 PA2 (io), 88 PA4/PGMNCMD (io), 89 PA5/PGMRDY (io), 90 PA6/PGMNOE (io), 91 PA7/PGMNVALID (io)
part B pins: 1 ADVREF (in), 57 NRST (io), 58 TST (in), 92 ERASE (in), 93 DDM (io), 94 DDP (io), 97 XIN/PGMCK (in), 98 XOUT (out), 99 PLLRC (in)
part C pins: 51 TDI (in), 76 TDO (out), 77 JTAGSEL (in), 78 TMS (in), 79 TCK (in)
part D pins: 2 GND (power), 7 VDDOUT (power), 8 VDDIN (power), 15 VDDCORE (power), 16 GND (power), 17 VDDIO (power), 32 GND (power), 33 VDDIO (power), 37 VDDCORE (power), 48 VDDIO (power), 52 GND (power), 61 VDDIO (power), 62 VDDCORE (power), 68 GND (power), 83 GND (power), 84 VDDIO (power), 87 VDDCORE (power), 95 VDDFLASH (power), 96 GND (power), 100 VDDPLL (power)

## AT91SAM7XC256-AU
designator U?
Smart ARM Microcontroller, ARM7TDMI 32-Bit RISC CPU, 256KB Flash and 64KB SRAM, 100-Pin LQFP, Industrial, Pb-Free
footprint LQFP100_N (Thin QFP, 100-Leads, Body 14x14mm, Pitch 0.5mm, IPC Medium Density)
footprint LQFP100_L (Thin QFP, 100-Leads, Body 14x14mm, Pitch 0.5mm, IPC High Density)
footprint LQFP100_M (Thin QFP, 100-Leads, Body 14x14mm, Pitch 0.5mm, IPC Low Density)
part A pins: 3 AD4 (in), 4 AD5 (in), 5 AD6 (in), 6 AD7 (in), 9 PB27/AD0 (io), 10 PB28/AD1 (io), 11 PB29/AD2 (io), 12 PB30/AD3 (io), 13 PA8/PGMM0 (io), 14 PA9/PGMM1 (io), 18 PA10/PGMM2 (io), 19 PA11/PGMM3 (io), 20 PA12/PGMD0 (io), 21 PA13/PGMD1 (io), 22 PA14/PGMD2 (io), 23 PA15/PGMD3 (io), 24 PA16/PGMD4 (io), 25 PA17/PGMD5 (io), 26 PA18/PGMD6 (io), 27 PB9 (io), 28 PB8 (io), 29 PB14 (io), 30 PB13 (io), 31 PB6 (io), 34 PB5 (io), 35 PB15 (io), 36 PB17 (io), 38 PB7 (io), 39 PB12 (io), 40 PB0 (io), 41 PB1 (io), 42 PB2 (io), 43 PB3 (io), 44 PB10 (io), 45 PB11 (io), 46 PA19/PGMD7 (io), 47 PA20/PGMD8 (io), 49 PA21/PGMD9 (io), 50 PA22/PGMD10 (io), 53 PB16 (io), 54 PB4 (io), 55 PA23/PGMD11 (io), 56 PA24/PGMD12 (io), 59 PA25/PGMD13 (io), 60 PA26/PGMD14 (io), 63 PB18 (io), 64 PB19 (io), 65 PB20 (io), 66 PB21 (io), 67 PB22 (io), 69 PB23 (io), 70 PB24 (io), 71 PB25 (io), 72 PB26 (io), 73 PA27/PGMD15 (io), 74 PA28 (io), 75 PA29 (io), 80 PA30 (io), 81 PA0/PGMEN0 (io), 82 PA1/PGMEN1 (io), 85 PA3 (io), 86 PA2 (io), 88 PA4/PGMNCMD (io), 89 PA5/PGMRDY (io), 90 PA6/PGMNOE (io), 91 PA7/PGMNVALID (io)
part B pins: 1 ADVREF (in), 57 NRST (io), 58 TST (in), 92 ERASE (in), 93 DDM (io), 94 DDP (io), 97 XIN/PGMCK (in), 98 XOUT (out), 99 PLLRC (in)
part C pins: 51 TDI (in), 76 TDO (out), 77 JTAGSEL (in), 78 TMS (in), 79 TCK (in)
part D pins: 2 GND (power), 7 VDDOUT (power), 8 VDDIN (power), 15 VDDCORE (power), 16 GND (power), 17 VDDIO (power), 32 GND (power), 33 VDDIO (power), 37 VDDCORE (power), 48 VDDIO (power), 52 GND (power), 61 VDDIO (power), 62 VDDCORE (power), 68 GND (power), 83 GND (power), 84 VDDIO (power), 87 VDDCORE (power), 95 VDDFLASH (power), 96 GND (power), 100 VDDPLL (power)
